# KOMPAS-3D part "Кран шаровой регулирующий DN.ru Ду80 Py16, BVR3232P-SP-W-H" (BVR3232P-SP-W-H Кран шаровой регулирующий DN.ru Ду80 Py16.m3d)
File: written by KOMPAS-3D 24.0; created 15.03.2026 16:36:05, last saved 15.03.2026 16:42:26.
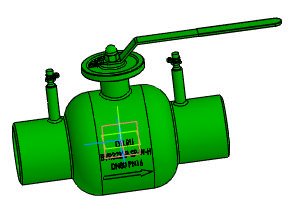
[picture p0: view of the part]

Document properties: Автор: Максим; Полное имя файла: D:\Rabota ebanaya\BVR3232P-SP-W-H Кран шаровой регулирующий Ду15-150\Типоразмеры\DN80\BVR3232P-SP-W-H Кран шаровой регулирующий DN.ru Ду80 Py16.m3d

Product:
- Body: Тело 1  | qty 1
    Масса: 16.412508
- Part/product: Кран шаровой регулирующий DN.ru Ду80 Py16  | designation BVR3232P-SP-W-H
    Масса: 7.8
    Раздел спецификации: Прочие изделия
    Примечание: D160-69413

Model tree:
1. Операция без истории:1

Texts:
  BVR3232P-SP-W-H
